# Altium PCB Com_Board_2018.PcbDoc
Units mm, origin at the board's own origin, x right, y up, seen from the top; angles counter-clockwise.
Board outline 152.45 x 155.55 mm, 2 copper layers (Top Layer, Bottom Layer), stack 1.57 mm thick; 25 components, 20 nets, 152 pads, 0 vias.
Unrouted connection lines stored in the file: 51.
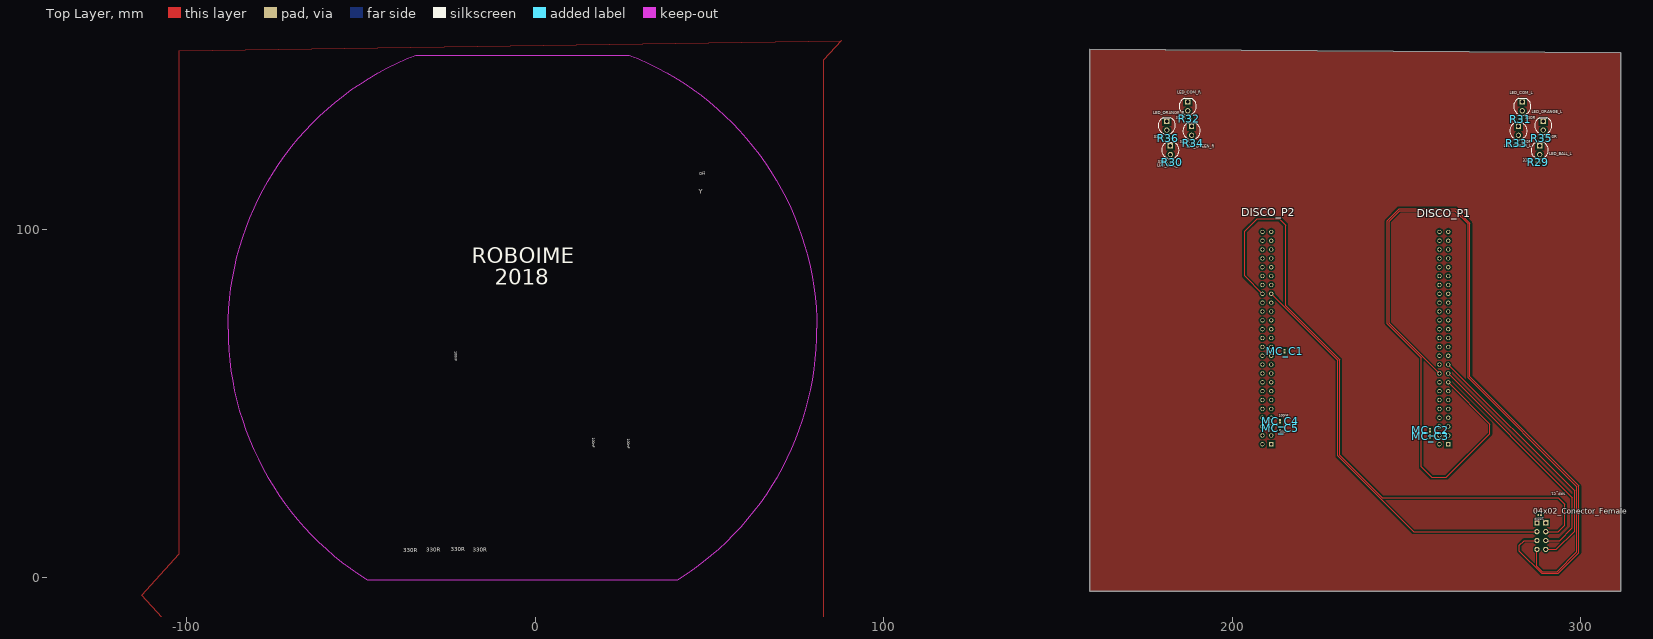
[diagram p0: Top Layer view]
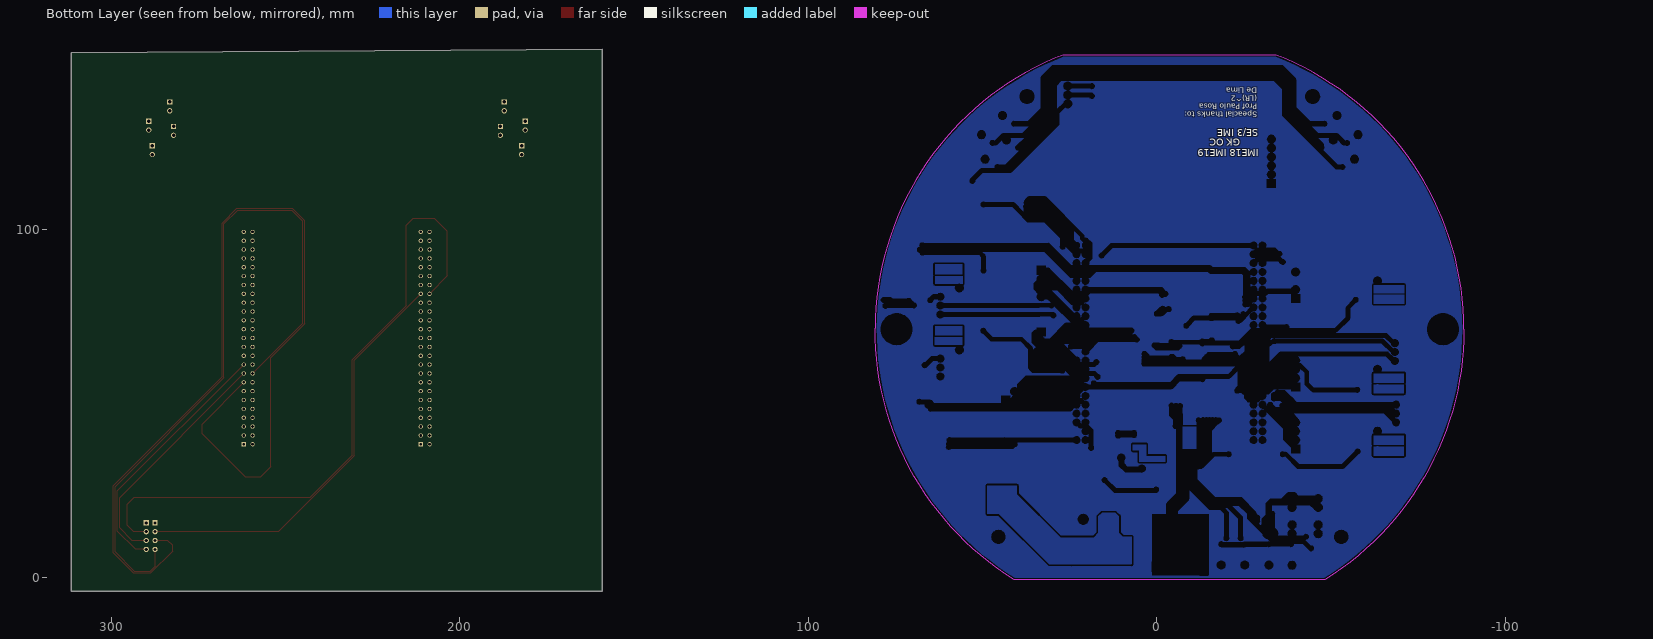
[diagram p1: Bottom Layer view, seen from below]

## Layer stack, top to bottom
Top Solder: solder mask 0.01, Solder Resist, Dk 3.5
Top Layer: signal copper 0.035
Dielectric 1: dielectric 1.5, FR-4, Dk 4.8
Bottom Layer: signal copper 0.035
Bottom Solder: solder mask 0.01, Solder Resist, Dk 3.5

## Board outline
159.125,151.674 159.125,-3.875 311.575,-3.875 311.575,6.45 311.575,150.549

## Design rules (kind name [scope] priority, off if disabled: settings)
Clearance Clearance_1 [All] p1: gap=0.3 ignorepadtopadclearanceinfootprint=FALSE except(0: Arc-Hole Track-Hole SMDPad-Hole THPad-Hole Via-Hole Fill-Hole Poly-Hole Region-Hole Text-Hole; 0.15: SMDPad-SMDPad; 0.2: Track-Track Track-SMDPad; 0.5: Arc-Poly Track-Poly SMDPad-Poly THPad-Poly Via-Poly Fill-Poly Poly-Poly Poly-Region Poly-Text)
HoleSize [All] p1: absolutevalues=TRUE maxlimit=10 minlimit=0.025 maxpercent=80.000 minpercent=20.000
MinimumSolderMaskSliver [All] p1 off: minsoldermaskwidth=0.2
PlaneConnect [All] p1: planeconnectstyle=Direct reliefexpansion=0.508 reliefentries=4 reliefconductorwidth=0.254 reliefairgap=0.254
PolygonConnect PolygonConnect_3 [InNet('GND')] p1: connectstyle=Direct reliefconductorwidth=0.254 reliefentries=4 polygonreliefangle="90 Angle" airgapwidth=0.254
PolygonConnect PolygonConnect_1 [InNetClass('DIRECT')] p2: connectstyle=Direct reliefconductorwidth=0.508 reliefentries=4 polygonreliefangle="90 Angle" airgapwidth=0.254
PolygonConnect PolygonConnect_2 [IsVia] p3: connectstyle=Direct reliefconductorwidth=0.254 reliefentries=4 polygonreliefangle="90 Angle" airgapwidth=0.254
PolygonConnect [All] p4: connectstyle=Direct reliefconductorwidth=0.3 reliefentries=4 polygonreliefangle="90 Angle" airgapwidth=0.254
RoutingVias [All] p1: holewidth=0.7 width=1 viastyle="Through Hole" minholewidth=0.5 minwidth=0.7 maxholewidth=6 maxwidth=6
SilkToSilkClearance [All] p1 off: silktosilkclearance=0.254
SilkToSolderMaskClearance [IsPad] p1 off: minsilkscreentomaskgap=0.254 clearancetoexposedcopper=TRUE
SolderMaskExpansion [All] p1: expansion=0.102
Width [All] p1: maxlimit=1.016 minlimit=0.2 preferedwidth=0.3
25 further rules are at their usual default settings.

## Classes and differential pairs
component class Periféricos: LED_BALL_L LED_BALL_R LED_COM_L LED_COM_R LED_GREEN_L LED_GREEN_R LED_ORAn_L LED_ORANGE_L LED_ORANGE_R R29 R30 R31 R32 R33 R34 R35 R36
component class Com_board_2018: 4k7 04x02_Conector_Female CON_DM CON_DMc DISCO_P1 DISCO_P2 Kick? MC_C1 MC_C2 MC_C3 MC_C4 MC_C5 NRF_C1 SENSOR1 SENSOR2

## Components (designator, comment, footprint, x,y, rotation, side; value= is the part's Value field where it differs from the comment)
04x02_Conector_Female "PPPC042LFBN-RC" 04x02_Conector_Female 288.716,11.887 r90 top
DISCO_P1 "SFH11-PBPC-D25-ST-BK" 25x02_Conector_Female 260.732,68.724 r90 top locked
DISCO_P2 "SFH11-PBPC-D25-ST-BK" 25x02_Conector_Female 209.932,68.724 r90 top locked
LED_BALL_L "LED" LED-5MM-PCB 288.25,122.662 r90 top
LED_BALL_R "LED" LED-5MM-PCB 182.25,122.662 r90 top
LED_COM_L "LED" LED-5MM-PCB 283.25,135.204 r90 top
LED_COM_R "LED" LED-5MM-PCB 187.25,135.204 r90 top
LED_GREEN_L "LED" LED-5MM-PCB 282.15,128.185 r90 top
LED_GREEN_R "LED" LED-5MM-PCB 188.35,128.185 r90 top
LED_ORANGE_L "LED" LED-5MM-PCB 289.275,129.7 r90 top
LED_ORANGE_R "LED" LED-5MM-PCB 181.225,129.7 r90 top
MC_C1 "100nF" 0402-CAP 215.012,64.954 r270 top value=100n
MC_C2 "100nF" 0402-CAP 256.795,42.308 r270 top value=100n
MC_C3 "100nF" 0402-CAP 256.795,40.53 r270 top value=100n
MC_C4 "100nF" 0402-CAP 213.742,44.848 r270 top value=100n
MC_C5 "100nF" 0402-CAP 213.742,42.816 r90 top value=100n
NRF_C1 "100nF" 0402-CAP 288.208,17.983 r180 top value=100n
R29 "330R" 0402-RES-HD 287.775,119.125 r0 top value=330
R30 "330R" 0402-RES-HD 182.75,119.15 r180 top value=330
R31 "330R" 0402-RES-HD 282.825,131.55 r0 top value=330
R32 "330R" 0402-RES-HD 187.725,131.65 r180 top value=330
R33 "330R" 0402-RES-HD 281.675,124.625 r0 top value=330
R34 "330R" 0402-RES-HD 188.825,124.675 r180 top value=330
R35 "330R" 0402-RES-HD 288.85,126.075 r0 top value=330
R36 "330R" 0402-RES-HD 181.65,126.1 r180 top value=330

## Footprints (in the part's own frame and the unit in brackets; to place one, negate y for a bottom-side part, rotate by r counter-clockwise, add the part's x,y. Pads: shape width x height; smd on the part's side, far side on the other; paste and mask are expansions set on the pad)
04x02_Conector_Female [mm] "PPPC042LFBN-RC"
  round 1.5 hole 0.9: 0(-3.81,1.27) 1(-1.27,1.27) 2(1.27,1.27) 4(-3.81,-1.27) 5(-1.27,-1.27) 6(1.27,-1.27)
  rect 1.5x1.5 hole 0.9: 3(3.81,1.27) 7(3.81,-1.27)
  body extent -5.3,-2.55 5.36,2.53, height 8.52
25x02_Conector_Female [mil] "SFH11-PBPC-D25-ST-BK"
  rect 47.25x47.25 hole 31.5: 1(-1200,-50)
  round 47.25 hole 31.5: 2(-1200,50) 3(-1100,-50) 4(-1100,50) 5(-1000,-50) 6(-1000,50) 7(-900,-50) 8(-900,50) 9(-800,-50) 10(-800,50) 11(-700,-50) 12(-700,50) 13(-600,-50) 14(-600,50) 15(-500,-50) 16(-500,50) 17(-400,-50) 18(-400,50) 19(-300,-50) 20(-300,50) 21(-200,-50) 22(-200,50) 23(-100,-50) 24(-100,50) 25(0,-50) 26(0,50) 27(100,-50) 28(100,50) 29(200,-50) 30(200,50) 31(300,-50) 32(300,50) 33(400,-50) 34(400,50) 35(500,-50) 36(500,50) 37(600,-50) 38(600,50) 39(700,-50) 40(700,50) 41(800,-50) 42(800,50) 43(900,-50) 44(900,50) 45(1000,-50) 46(1000,50) 47(1100,-50) 48(1100,50) 49(1200,-50) 50(1200,50)
  body extent -1350,-121 1350,115, height 333
0402-CAP [mm] "Chip Capacitor, Body 1.0x0.5mm, Height 0.6mm, IPC Medium Density"
  rect 0.52x0.52 smd: 1(-0.4,0) 2(0.4,0)
  body extent -0.55,-0.3 0.55,0.3, height 0.33
0402-RES-HD [mm] "Chip Resistor, Body 1.0x0.5mm, IPC High Density"
  rect 0.45x0.55 smd: 1(-0.45,0) 2(0.45,0)
  body extent -0.52,-0.27 0.53,0.28, height 0.4
LED-5MM-PCB [mm]
  rect 1.5x1.5 hole 1: 1(1.27,0)
  round 1.5 hole 1: 2(-1.27,0)
  silkscreen extent -2.5,-2.5 2.28,2.5, body extent -2.98,-3.01 2.44,3.01, height 8.59

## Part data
04x02_Conector_Female: library part 04x02_Conector_Female, "8 Position Header Connector 0.100\" (2.54mm) Through Hole Gold"
DISCO_P1 DISCO_P2: library part 25x02_Conector_Female, "50 Position Header Connector 0.100\" (2.54mm) Through Hole Gold"
LED_BALL_L LED_BALL_R LED_COM_L LED_COM_R LED_GREEN_L LED_GREEN_R LED_ORANGE_L LED_ORANGE_R: library part LED-5MM-3, "LED 5MM PTH"
MC_C1 MC_C2 MC_C3 MC_C4 MC_C5 NRF_C1: library part CC0402-100nF-A.12, "CAP CER 0.1UF 10V 20% X5R 0402", Part No=VJ0402V104ZXQPBC
R29 R30 R31 R32 R33 R34 R35 R36: library part R0402-330R-7, "RES 330 OHM 1/10W 1% 0402 SMD", Part No=ERJ-2RKF3300X

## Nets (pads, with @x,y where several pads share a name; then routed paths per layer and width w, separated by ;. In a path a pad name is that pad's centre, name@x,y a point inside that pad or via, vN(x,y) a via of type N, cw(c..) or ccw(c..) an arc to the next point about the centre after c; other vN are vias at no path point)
Blue_led: DISCO_P1.47 R31.1 R32.1
GND: 04x02_Conector_Female.3 DISCO_P1.1 DISCO_P1.2 DISCO_P1.5 DISCO_P1.23 DISCO_P1.49 DISCO_P1.50 DISCO_P2.1 DISCO_P2.2 DISCO_P2.49 DISCO_P2.50 LED_BALL_L.1 LED_BALL_R.1 LED_COM_L.1 LED_COM_R.1 LED_GREEN_L.1 LED_GREEN_R.1 LED_ORANGE_L.1 LED_ORANGE_R.1 MC_C1.1 MC_C2.1 MC_C3.2 MC_C4.1 MC_C5.1 NRF_C1.2
LED_G: DISCO_P1.44 R33.1 R34.1
LED_O: DISCO_P1.45 R35.1 R36.1
LED_R: DISCO_P1.46 R29.1 R30.1
NetLED_BALL_L_2: LED_BALL_L.2 R29.2
NetLED_BALL_R_2: LED_BALL_R.2 R30.2
NetLED_COM_L_2: LED_COM_L.2 R31.2
NetLED_COM_R_2: LED_COM_R.2 R32.2
NetLED_GREEN_L_2: LED_GREEN_L.2 R33.2
NetLED_GREEN_R_2: LED_GREEN_R.2 R34.2
NetLED_ORANGE_L_2: LED_ORANGE_L.2 R35.2
NetLED_ORANGE_R_2: LED_ORANGE_R.2 R36.2
NRF_CE: 04x02_Conector_Female.2 DISCO_P2.35 | length 120.6
  Top Layer w0.3: DISCO_P2.35 230.325,62.301 230.325,34.875 252.043,13.157 04x02_Conector_Female.2
NRF_CS#: 04x02_Conector_Female.6 DISCO_P2.36 | length 189.2
  Top Layer w0.3: DISCO_P2.36 203.55,86.536 203.55,99.325 207.175,102.95 213.55,102.95 215.35,101.15 215.35,77.983 230.825,62.508 230.825,35.082 243.032,22.875 293.6,22.875 295.425,21.05 295.425,15.014 293.568,13.157 04x02_Conector_Female.6
NRF_IRQ: 04x02_Conector_Female.4 DISCO_P1.19 | length 73.3
  Top Layer w0.3: DISCO_P1.19 298.25,24.856 298.25,13.275 293.052,8.077 04x02_Conector_Female.4
SPI1_MISO: 04x02_Conector_Female.0 DISCO_P1.18 | length 201.6
  Top Layer w0.3: DISCO_P1.18 245,73.026 245,102.175 248.1,105.275 263.925,105.275 267.675,101.525 267.675,57.375 298.95,26.1 298.95,7.35 293.3,1.7 288.975,1.7 287.446,3.229 04x02_Conector_Female.0
SPI1_MOSI: 04x02_Conector_Female.5 DISCO_P1.17 | length 68.2
  Top Layer w0.3: DISCO_P1.17 297.625,22.941 297.625,14.259 293.983,10.617 04x02_Conector_Female.5
SPI1_SCK: 04x02_Conector_Female.1 DISCO_P1.15 | length 284.1
  Top Layer w0.3: DISCO_P1.15 273.975,44.051 273.975,41.325 261.475,28.825 257.225,28.825 254.3,31.75 254.3,63.018 244.5,72.818 244.5,102.382 247.893,105.775 264.132,105.775 268.175,101.732 268.175,57.582 299.45,26.307 299.45,7.143 293.507,1.2 288.768,1.2 282.45,7.518 282.45,9.25 283.817,10.617 04x02_Conector_Female.1
VCC: 04x02_Conector_Female.7 DISCO_P1.3 DISCO_P1.4 DISCO_P2.5 DISCO_P2.6 DISCO_P2.22 MC_C1.2 MC_C2.2 MC_C3.1 MC_C4.2 MC_C5.2 NRF_C1.1
pads on no net: DISCO_P1.6 DISCO_P1.7 DISCO_P1.8 DISCO_P1.9 DISCO_P1.10 DISCO_P1.11 DISCO_P1.12 DISCO_P1.13 DISCO_P1.14 DISCO_P1.16 DISCO_P1.20 DISCO_P1.21 DISCO_P1.22 DISCO_P1.24 DISCO_P1.25 DISCO_P1.26 DISCO_P1.27 DISCO_P1.28 DISCO_P1.29 DISCO_P1.30 DISCO_P1.31 DISCO_P1.32 DISCO_P1.33 DISCO_P1.34 DISCO_P1.35 DISCO_P1.36 DISCO_P1.37 DISCO_P1.38 DISCO_P1.39 DISCO_P1.40 DISCO_P1.41 DISCO_P1.42 DISCO_P1.43 DISCO_P1.48 DISCO_P2.3 DISCO_P2.4 DISCO_P2.7 DISCO_P2.8 DISCO_P2.9 DISCO_P2.10 DISCO_P2.11 DISCO_P2.12 DISCO_P2.13 DISCO_P2.14 DISCO_P2.15 DISCO_P2.16 DISCO_P2.17 DISCO_P2.18 DISCO_P2.19 DISCO_P2.20 DISCO_P2.21 DISCO_P2.23 DISCO_P2.24 DISCO_P2.25 DISCO_P2.26 DISCO_P2.27 DISCO_P2.28 DISCO_P2.29 DISCO_P2.30 DISCO_P2.31 DISCO_P2.32 DISCO_P2.33 DISCO_P2.34 DISCO_P2.37 DISCO_P2.38 DISCO_P2.39 DISCO_P2.40 DISCO_P2.41 DISCO_P2.42 DISCO_P2.43 DISCO_P2.44 DISCO_P2.45 DISCO_P2.46 DISCO_P2.47 DISCO_P2.48

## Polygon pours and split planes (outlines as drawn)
no net on Top Layer (solid, pour order 133): 320.1,155.1
no net on Top Layer (solid, pour order 131): 159.075,151.525 159.275,151.325 159.275,-3.825 311.35,-3.825 311.35,150.425
GND on Top Layer "Top Layer-No Net" (solid, remove dead copper, shelved, pour order 123): 87.747,154.115 82.647,148.506 82.647,-11.516 -107.068,-11.516 -112.961,-5.036 -102.195,6.804 -102.195,151.123
GND on Bottom Layer "Top Layer-No Net" (solid, remove dead copper, pour order 112): 114.671,161.862 114.671,-14.668 114.925,-14.922 109.972,-19.875 -107.579,-19.875 -107.579,147.892 -98.181,157.29
no net on Bottom Layer "Top Layer-No Net" (solid, remove dead copper, pour order 28): 45.253,18.3 48.575,18.3 48.575,26.353 40.136,26.353 40.136,23.936 27.718,11.518 18.04,11.483 16.707,12.817 16.707,17.516 15.691,18.532 11.881,18.532 10.865,17.643 10.865,12.817 9.722,11.674 7.182,11.674 7.182,3.8 11.119,3.816 24.454,3.816 24.47,3.8 30.829,3.876
no net on Bottom Layer "Top Layer-No Net" (solid, remove dead copper, pour order 19): 63.622,69.34 58.542,69.34 55.748,69.34 55.748,66.8 58.542,66.8 63.622,66.8
no net on Bottom Layer "Top Layer-No Net" (solid, remove dead copper, pour order 18): 63.614,72.076 58.611,72.076 55.74,72.076 55.74,69.475 58.55,69.475 63.614,69.475
no net on Bottom Layer "Top Layer-No Net" (solid, remove dead copper, pour order 17): 63.576,86.99 58.496,86.99 55.702,86.99 55.702,84.3 63.576,84.3
no net on Bottom Layer "Top Layer-No Net" (solid, remove dead copper, pour order 16): 63.614,89.87 55.74,89.87 55.74,87 58.534,87 63.614,87
no net on Bottom Layer "Top Layer-No Net" (solid, remove dead copper, pour order 9): -70.969,34.951 -70.969,37.89 -65.889,37.89 -62.281,37.89 -62.281,34.951
no net on Bottom Layer "Top Layer-No Net" (solid, remove dead copper, pour order 8): -70.957,38.075 -70.957,40.754 -62.269,40.754 -62.269,38.075
no net on Bottom Layer "Top Layer-No Net" (solid, remove dead copper, pour order 7): -70.925,52.875 -70.925,55.59 -65.845,55.59 -62.237,55.59 -62.237,52.875
no net on Bottom Layer "Top Layer-No Net" (solid, remove dead copper, pour order 6): -70.969,55.9 -70.969,58.525 -62.281,58.525 -62.281,55.9
no net on Bottom Layer "Top Layer-No Net" (solid, remove dead copper, pour order 5): -71.003,83.882 -62.315,83.882 -62.315,81.342 -71.003,81.342
no net on Bottom Layer "Top Layer-No Net" (solid, remove dead copper, pour order 4): -71.019,78.6 -62.331,78.6 -62.331,81.14 -71.019,81.14
no net on Bottom Layer "Top Layer-No Net" (solid, remove dead copper, pour order 70): 6.848,38.164 6.848,36.513 4.943,36.513 4.943,33.295 -2.423,33.295 -2.423,34.862 3.038,34.862 3.038,38.164 6.721,38.164
VCC on Bottom Layer "Top Layer-No Net" (solid, remove dead copper, pour order 80): -7.503,43.244 -11.313,43.244 -11.313,36.894 -7.503,36.894

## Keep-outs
Keep-Out Layer:
  lines w0.05: -88.193,71.184 -88.14,74.166 -87.982,77.144 -87.72,80.115 -87.352,83.075 -86.88,86.021 -86.305,88.947 -85.626,91.852 -84.846,94.731 -83.964,97.58 -82.983,100.397 -81.902,103.177 -80.724,105.917 -79.451,108.614 -78.082,111.264 -76.621,113.865 -75.07,116.412 -73.429,118.903 -71.701,121.335 -69.889,123.704 -67.994,126.007 -66.019,128.242 -63.967,130.406 -61.839,132.497 -59.639,134.511 -57.369,136.446 -55.032,138.299 -52.631,140.069 -50.17,141.754 -47.65,143.35 -45.076,144.857 -42.45,146.271 -39.776,147.592 -37.057,148.818 -34.296,149.947 26.91,149.947 29.661,148.822 32.37,147.602 35.035,146.286 37.652,144.878 40.218,143.378 42.729,141.79 45.183,140.114 47.577,138.352 49.907,136.508 52.171,134.583 54.366,132.579 56.489,130.5 58.537,128.347 60.509,126.123 62.401,123.831 64.212,121.475 65.938,119.056 67.578,116.578 69.131,114.043 70.593,111.456 71.963,108.819 73.24,106.135 74.421,103.409 75.506,100.642 76.493,97.839 77.38,95.003 78.168,92.137 78.854,89.245 79.438,86.332 79.919,83.399 80.297,80.451 80.571,77.492 80.741,74.525 80.806,71.554 80.767,68.582 80.623,65.614 80.375,62.653 80.023,59.702 79.568,56.765 79.009,53.846 78.349,50.949 77.586,48.076 76.723,45.233 75.761,42.421 74.701,39.645 73.543,36.908 72.29,34.213 70.943,31.564 69.504,28.964 67.974,26.416 66.355,23.924 64.65,21.49 62.86,19.117 60.988,16.809 59.036,14.568 57.007,12.398 54.902,10.299 52.725,8.277 50.478,6.332 48.164,4.467 45.786,2.685 43.347,0.987 40.849,-0.623 -48.235,-0.623 -50.722,0.98 -53.151,2.67 -55.52,4.443 -57.825,6.299 -60.063,8.234 -62.233,10.246 -64.33,12.333 -66.354,14.493 -68.3,16.721 -70.168,19.017 -71.953,21.376 -73.655,23.797 -75.272,26.275 -76.8,28.809 -78.239,31.395 -79.586,34.029 -80.841,36.709 -82,39.431 -83.064,42.193 -84.031,44.99 -84.898,47.818 -85.667,50.676 -86.334,53.559 -86.901,56.463 -87.365,59.385 -87.727,62.322 -87.986,65.27 -88.141,68.225 -88.193,71.184

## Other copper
Top Layer:
  region: -133.25,79.25
Bottom Layer:
  pour cut-out: -14.975,18.175 -14.975,0.7 1.275,0.7 1.275,18.175

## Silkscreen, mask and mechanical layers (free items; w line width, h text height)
Top Overlay:
  text "Off" at 47.075,115.225 h1.4
  text "Y" at 46.9,110.075 h1.4
  text "ROBOIME" at -18.25,90.225 h4.5
  text "2018" at -11.575,83.975 h4.5
  text "100nF" at -23.375,65 h1.2 r270
  text "100nF" at 15.992,40.069 h1.2 r270
  text "100nF" at 26.025,39.815 h1.2 r270
  text "330R" at -24.298,7.099 h2
  text "330R" at -31.273,6.999 h2
  text "330R" at -17.973,6.999 h2
  text "330R" at -37.9,6.825 h2
Bottom Overlay:
  text "Speacial thanks to: / Prof Paulo Rosa / (LR)^2 / De Lima" at -28.839,140.526 h1.52 r180
  text "SE/3 IME" at -29.093,128.715 h2 r180
  text "GK OC" at -23.925,125.95 h2 r180
  text "IME18 IME19" at -29.35,122.925 h2 r180
Mechanical 1:
  lines w0.5: -88.275,71.261 -88.223,68.302 -88.068,65.347 -87.809,62.4 -87.447,59.463 -86.983,56.541 -86.417,53.636 -85.749,50.753 -84.98,47.896 -84.113,45.067 -83.146,42.27 -82.082,39.509 -80.923,36.787 -79.668,34.107 -78.321,31.472 -76.882,28.886 -75.354,26.353 -73.737,23.874 -72.035,21.454 -70.25,19.094 -68.382,16.799 -66.436,14.57 -64.412,12.411 -62.315,10.324 -60.145,8.312 -57.907,6.376 -55.602,4.521 -53.233,2.747 -50.804,1.058 -48.317,-0.546 40.767,-0.546 43.265,1.065 45.704,2.762 48.082,4.544 50.396,6.409 52.643,8.354 54.82,10.377 56.925,12.475 58.954,14.646 60.906,16.887 62.778,19.195 64.568,21.567 66.273,24.001 67.892,26.494 69.422,29.041 70.861,31.641 72.208,34.29 73.461,36.985 74.619,39.722 75.679,42.498 76.641,45.31 77.504,48.154 78.266,51.026 78.927,53.924 79.486,56.843 79.941,59.779 80.293,62.73 80.541,65.692 80.685,68.66 80.724,71.632 80.659,74.603 80.489,77.57 80.215,80.529 79.837,83.476 79.356,86.409 78.772,89.323 78.086,92.214 77.298,95.08 76.411,97.916 75.424,100.719 74.339,103.486 73.158,106.213 71.881,108.897 70.511,111.534 69.049,114.121 67.496,116.655 65.856,119.133 64.13,121.552 62.319,123.909 60.427,126.201 58.455,128.424 56.407,130.577 54.284,132.657 52.089,134.66 49.825,136.585 47.495,138.43 45.101,140.191 42.647,141.867 40.136,143.456 37.57,144.955 34.953,146.364 32.288,147.679 29.579,148.9 26.828,150.025 -34.378,150.025 -37.139,148.896 -39.858,147.67 -42.532,146.349 -45.158,144.934 -47.732,143.428 -50.252,141.831 -52.713,140.147 -55.114,138.377 -57.451,136.523 -59.721,134.588 -61.921,132.574 -64.049,130.484 -66.101,128.32 -68.076,126.084 -69.971,123.781 -71.783,121.412 -73.511,118.981 -75.152,116.49 -76.703,113.942 -78.164,111.342 -79.533,108.692 -80.806,105.995 -81.984,103.254 -83.065,100.474 -84.046,97.657 -84.928,94.808 -85.708,91.929 -86.387,89.025 -86.962,86.098 -87.434,83.153 -87.802,80.193 -88.065,77.222 -88.222,74.243 -88.275,71.261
